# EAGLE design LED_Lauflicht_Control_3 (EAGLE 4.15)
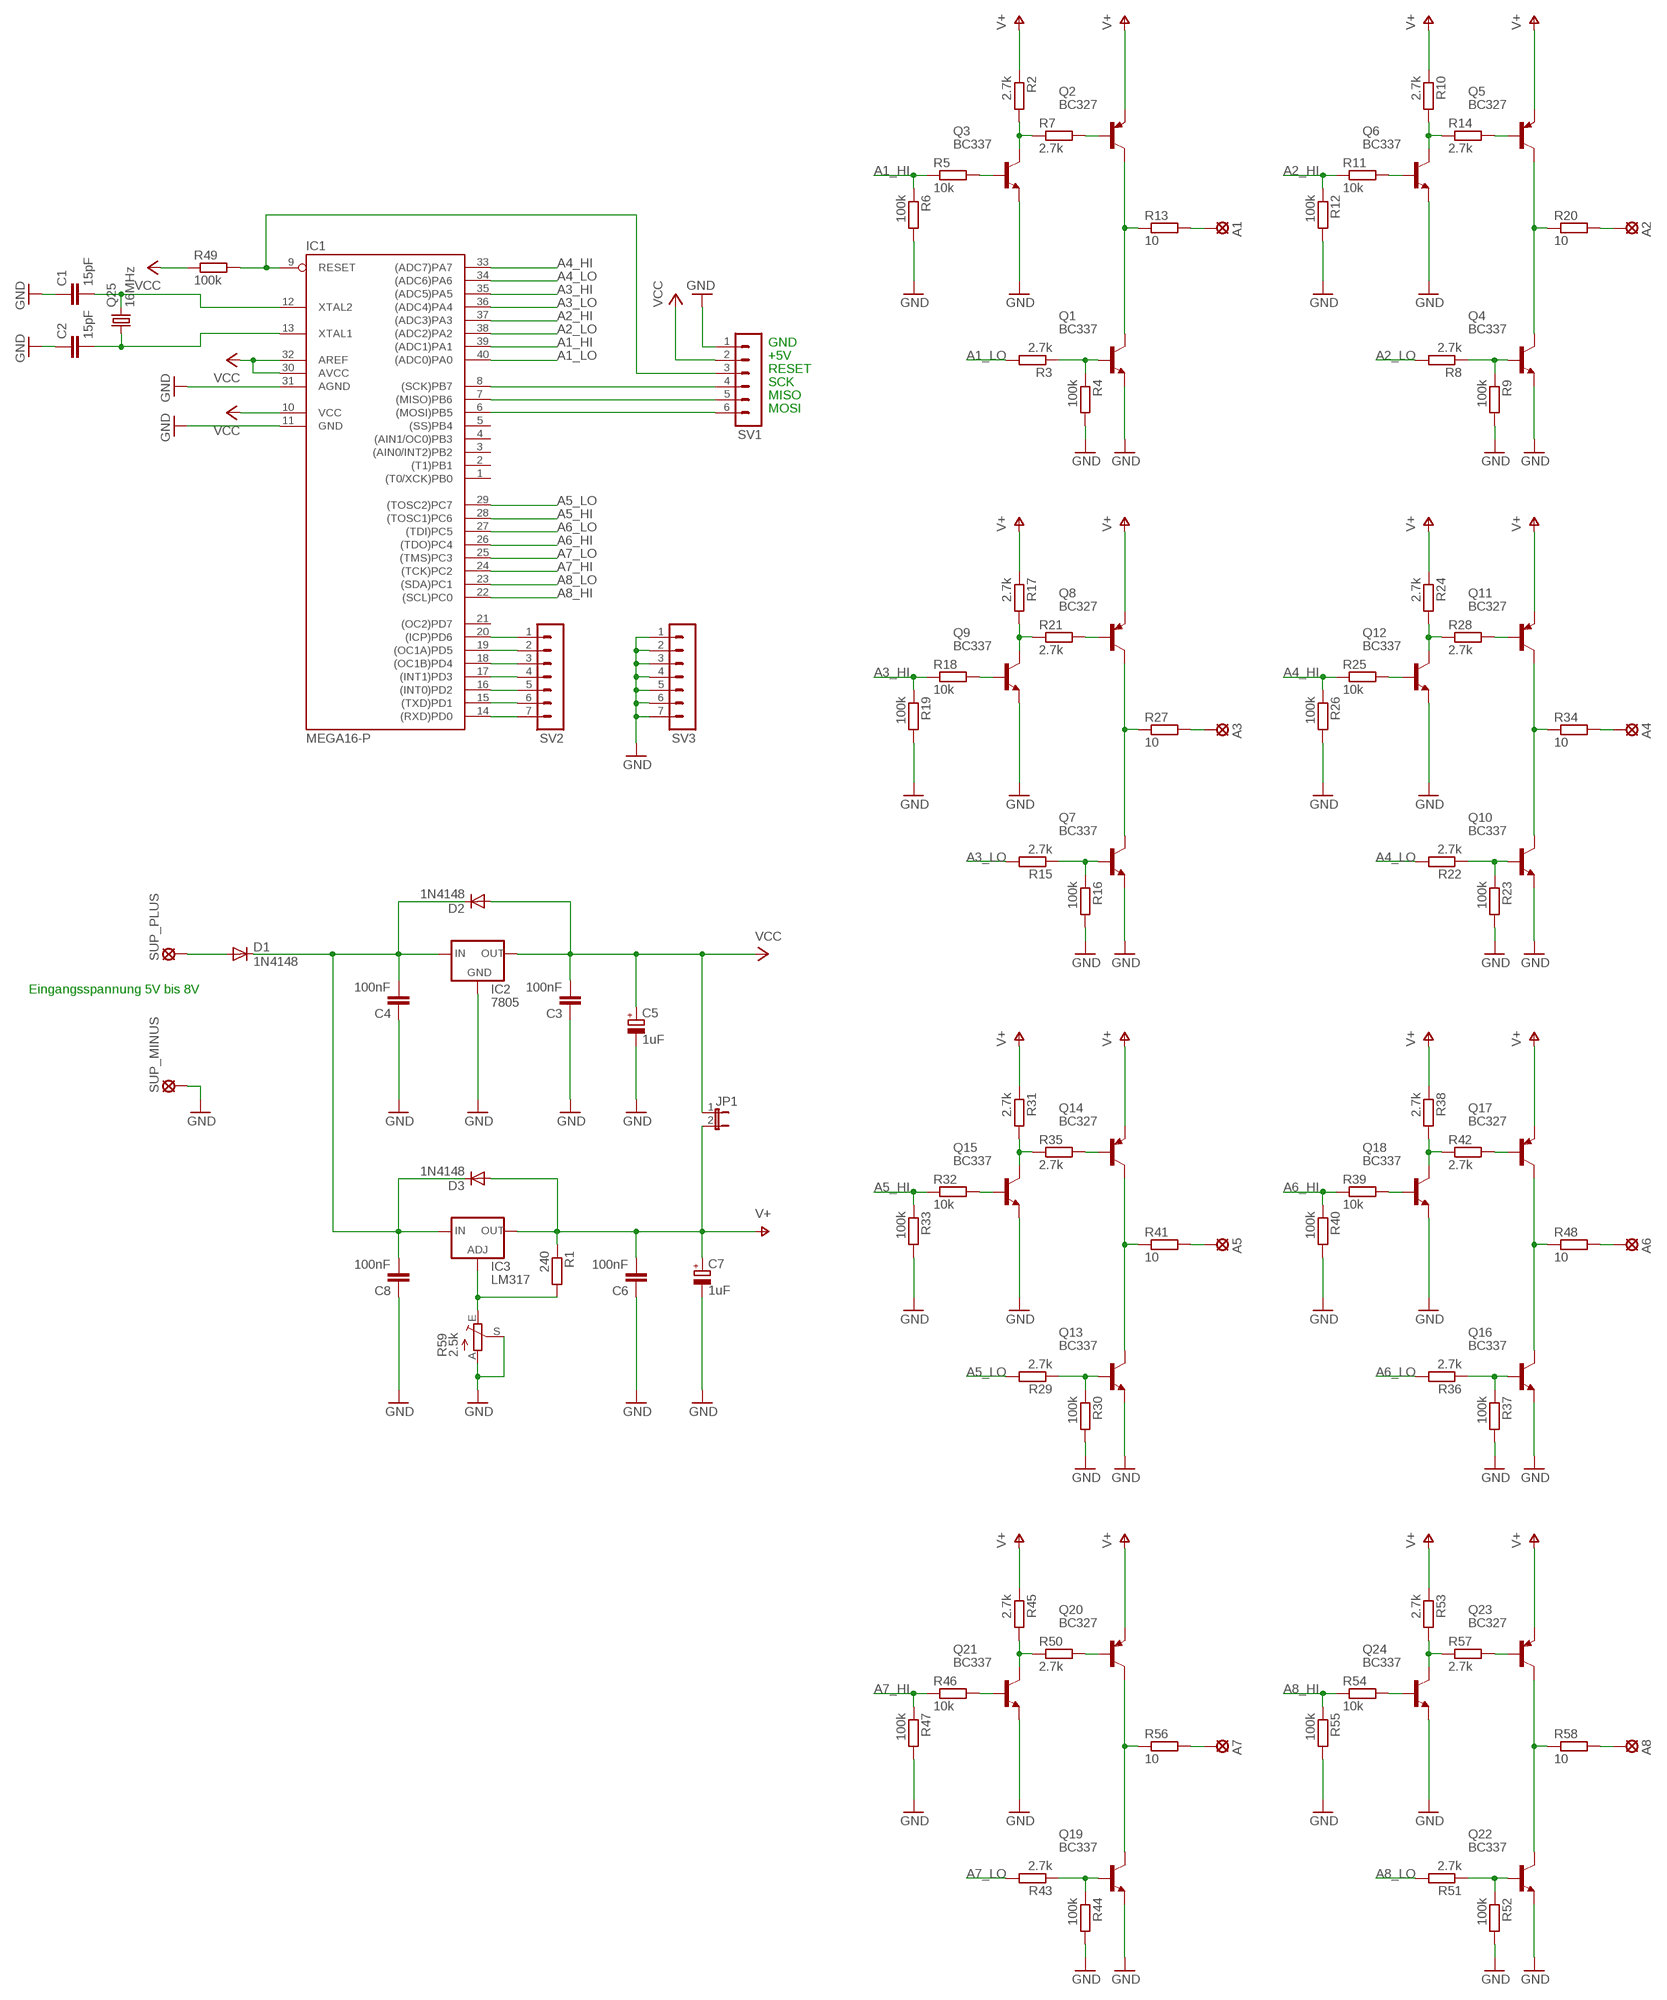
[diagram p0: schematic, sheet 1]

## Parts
A1  LSP13  [LSP13]
A2  LSP13  [LSP13]
A3  LSP13  [LSP13]
A4  LSP13  [LSP13]
A5  LSP13  [LSP13]
A6  LSP13  [LSP13]
A7  LSP13  [LSP13]
A8  LSP13  [LSP13]
C1  15pF  C-EU050-025X075  [C050-025X075]
C2  15pF  C-EU050-025X075  [C050-025X075]
C3  100nF  C-EU050-025X075  [C050-025X075]
C4  100nF  C-EU050-025X075  [C050-025X075]
C5  1uF  CPOL-EUE5-10.5  [E5-10,5]
C6  100nF  C-EU050-025X075  [C050-025X075]
C7  1uF  CPOL-EUE5-10.5  [E5-10,5]
C8  100nF  C-EU050-025X075  [C050-025X075]
D1  1N4148  [DO35-10]
D2  1N4148  [DO35-10]
D3  1N4148  [DO35-10]
IC1  MEGA16-P  [DIL40]
IC2  7805  78XXL  [78XXL]
IC3  LM317  LM317TL  [317TL]
JP1  JP1E  [JP1]
Q1  BC337  BC549B  [TO92-EBC]
Q2  BC327  BC559B  [TO92-EBC]
Q3  BC337  BC549B  [TO92-EBC]
Q4  BC337  BC549B  [TO92-EBC]
Q5  BC327  BC559B  [TO92-EBC]
Q6  BC337  BC549B  [TO92-EBC]
Q7  BC337  BC549B  [TO92-EBC]
Q8  BC327  BC559B  [TO92-EBC]
Q9  BC337  BC549B  [TO92-EBC]
Q10  BC337  BC549B  [TO92-EBC]
Q11  BC327  BC559B  [TO92-EBC]
Q12  BC337  BC549B  [TO92-EBC]
Q13  BC337  BC549B  [TO92-EBC]
Q14  BC327  BC559B  [TO92-EBC]
Q15  BC337  BC549B  [TO92-EBC]
Q16  BC337  BC549B  [TO92-EBC]
Q17  BC327  BC559B  [TO92-EBC]
Q18  BC337  BC549B  [TO92-EBC]
Q19  BC337  BC549B  [TO92-EBC]
Q20  BC327  BC559B  [TO92-EBC]
Q21  BC337  BC549B  [TO92-EBC]
Q22  BC337  BC549B  [TO92-EBC]
Q23  BC327  BC559B  [TO92-EBC]
Q24  BC337  BC549B  [TO92-EBC]
Q25  16MHz  CRYTALHC18U-V  [HC18U-V]
R1  240  R-EU_0207/10  [0207/10]
R2  2.7k  R-EU_0207/10  [0207/10]
R3  2.7k  R-EU_0207/10  [0207/10]
R4  100k  R-EU_0207/10  [0207/10]
R5  10k  R-EU_0207/10  [0207/10]
R6  100k  R-EU_0207/10  [0207/10]
R7  2.7k  R-EU_0207/10  [0207/10]
R8  2.7k  R-EU_0207/10  [0207/10]
R9  100k  R-EU_0207/10  [0207/10]
R10  2.7k  R-EU_0207/10  [0207/10]
R11  10k  R-EU_0207/10  [0207/10]
R12  100k  R-EU_0207/10  [0207/10]
R13  10  R-EU_0207/10  [0207/10]
R14  2.7k  R-EU_0207/10  [0207/10]
R15  2.7k  R-EU_0207/10  [0207/10]
R16  100k  R-EU_0207/10  [0207/10]
R17  2.7k  R-EU_0207/10  [0207/10]
R18  10k  R-EU_0207/10  [0207/10]
R19  100k  R-EU_0207/10  [0207/10]
R20  10  R-EU_0207/10  [0207/10]
R21  2.7k  R-EU_0207/10  [0207/10]
R22  2.7k  R-EU_0207/10  [0207/10]
R23  100k  R-EU_0207/10  [0207/10]
R24  2.7k  R-EU_0207/10  [0207/10]
R25  10k  R-EU_0207/10  [0207/10]
R26  100k  R-EU_0207/10  [0207/10]
R27  10  R-EU_0207/10  [0207/10]
R28  2.7k  R-EU_0207/10  [0207/10]
R29  2.7k  R-EU_0207/10  [0207/10]
R30  100k  R-EU_0207/10  [0207/10]
R31  2.7k  R-EU_0207/10  [0207/10]
R32  10k  R-EU_0207/10  [0207/10]
R33  100k  R-EU_0207/10  [0207/10]
R34  10  R-EU_0207/10  [0207/10]
R35  2.7k  R-EU_0207/10  [0207/10]
R36  2.7k  R-EU_0207/10  [0207/10]
R37  100k  R-EU_0207/10  [0207/10]
R38  2.7k  R-EU_0207/10  [0207/10]
R39  10k  R-EU_0207/10  [0207/10]
R40  100k  R-EU_0207/10  [0207/10]
R41  10  R-EU_0207/10  [0207/10]
R42  2.7k  R-EU_0207/10  [0207/10]
R43  2.7k  R-EU_0207/10  [0207/10]
R44  100k  R-EU_0207/10  [0207/10]
R45  2.7k  R-EU_0207/10  [0207/10]
R46  10k  R-EU_0207/10  [0207/10]
R47  100k  R-EU_0207/10  [0207/10]
R48  10  R-EU_0207/10  [0207/10]
R49  100k  R-EU_0207/10  [0207/10]
R50  2.7k  R-EU_0207/10  [0207/10]
R51  2.7k  R-EU_0207/10  [0207/10]
R52  100k  R-EU_0207/10  [0207/10]
R53  2.7k  R-EU_0207/10  [0207/10]
R54  10k  R-EU_0207/10  [0207/10]
R55  100k  R-EU_0207/10  [0207/10]
R56  10  R-EU_0207/10  [0207/10]
R57  2.7k  R-EU_0207/10  [0207/10]
R58  10  R-EU_0207/10  [0207/10]
R59  2.5k  TRIM_EU-LI15  [LI15]
SUP_MINUS  LSP13  [LSP13]
SUP_PLUS  LSP13  [LSP13]
SV1  MA06-1  [MA06-1]
SV2  MA07-1  [MA07-1]
SV3  MA07-1  [MA07-1]

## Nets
A1_HI: IC1.39((ADC1)PA1) R5.1 R6.1
A1_LO: IC1.40((ADC0)PA0) R3.2
A2_HI: IC1.37((ADC3)PA3) R11.1 R12.1
A2_LO: IC1.38((ADC2)PA2) R8.2
A3_HI: IC1.35((ADC5)PA5) R18.1 R19.1
A3_LO: IC1.36((ADC4)PA4) R15.2
A4_HI: IC1.33((ADC7)PA7) R25.1 R26.1
A4_LO: IC1.34((ADC6)PA6) R22.2
A5_HI: IC1.28((TOSC1)PC6) R32.1 R33.1
A5_LO: IC1.29((TOSC2)PC7) R29.2
A6_HI: IC1.26((TDO)PC4) R39.1 R40.1
A6_LO: IC1.27((TDI)PC5) R36.2
A7_HI: IC1.24((TCK)PC2) R46.1 R47.1
A7_LO: IC1.25((TMS)PC3) R43.2
A8_HI: IC1.22((SCL)PC0) R54.1 R55.1
A8_LO: IC1.23((SDA)PC1) R51.2
GND: C1.1 C2.1 C3.1 C4.1 C5.- C6.1 C7.- C8.1 IC1.11(GND) IC1.31(AGND) IC2.GND Q1.E Q3.E Q4.E Q6.E Q7.E Q9.E Q10.E Q12.E Q13.E Q15.E Q16.E Q18.E Q19.E Q21.E Q22.E Q24.E R4.2 R6.2 R9.2 R12.2 R16.2 R19.2 R23.2 R26.2 R30.2 R33.2 R37.2 R40.2 R44.2 R47.2 R52.2 R55.2 R59.A R59.S SUP_MINUS.MP SV1.1 SV3.1 SV3.2 SV3.3 SV3.4 SV3.5 SV3.6 SV3.7
N$1: Q1.C Q2.C R13.1
N$2: Q3.C R2.2 R7.1
N$3: Q3.B R5.2
N$4: Q2.B R7.2
N$5: Q4.C Q5.C R20.1
N$6: Q6.C R10.2 R14.1
N$7: IC1.14((RXD)PD0) SV2.7
N$8: C4.2 C8.2 D1.C D2.C D3.C IC2.IN IC3.3(IN)
N$9: Q4.B R8.1 R9.1
N$10: Q6.B R11.2
N$11: Q5.B R14.2
N$12: Q7.C Q8.C R27.1
N$13: Q9.C R17.2 R21.1
N$14: IC1.15((TXD)PD1) SV2.6
N$15: Q7.B R15.1 R16.1
N$16: Q9.B R18.2
N$17: Q8.B R21.2
N$18: Q10.C Q11.C R34.1
N$19: Q12.C R24.2 R28.1
N$20: IC1.16((INT0)PD2) SV2.5
N$21: Q1.B R3.1 R4.1
N$22: Q10.B R22.1 R23.1
N$23: Q12.B R25.2
N$24: Q11.B R28.2
N$25: Q13.C Q14.C R41.1
N$26: Q15.C R31.2 R35.1
N$27: IC1.17((INT1)PD3) SV2.4
N$28: Q13.B R29.1 R30.1
N$29: Q15.B R32.2
N$30: Q14.B R35.2
N$31: Q16.C Q17.C R48.1
N$32: Q18.C R38.2 R42.1
N$33: IC1.18((OC1B)PD4) SV2.3
N$34: Q16.B R36.1 R37.1
N$35: Q18.B R39.2
N$36: Q17.B R42.2
N$37: Q19.C Q20.C R56.1
N$38: C1.2 IC1.12(XTAL2) Q25.2
N$39: IC1.9(RESET) R49.2 SV1.3
N$40: Q21.C R45.2 R50.1
N$41: IC1.19((OC1A)PD5) SV2.2
N$42: Q19.B R43.1 R44.1
N$43: C2.2 IC1.13(XTAL1) Q25.1
N$44: IC1.7((MISO)PB6) SV1.5
N$45: Q21.B R46.2
N$46: IC1.8((SCK)PB7) SV1.4
N$47: Q20.B R50.2
N$48: Q22.C Q23.C R58.1
N$49: IC1.6((MOSI)PB5) SV1.6
N$50: Q24.C R53.2 R57.1
N$51: IC1.20((ICP)PD6) SV2.1
N$52: Q22.B R51.1 R52.1
N$53: Q24.B R54.2
N$54: Q23.B R57.2
N$55: D1.A SUP_PLUS.MP
N$56: A1.MP R13.2
N$57: A2.MP R20.2
N$58: A3.MP R27.2
N$59: A4.MP R34.2
N$60: A5.MP R41.2
N$61: A6.MP R48.2
N$62: A7.MP R56.2
N$63: A8.MP R58.2
N$65: IC3.1(ADJ) R1.2 R59.E
V+: C6.2 C7.+ D3.A IC3.2(OUT) JP1.2 Q2.E Q5.E Q8.E Q11.E Q14.E Q17.E Q20.E Q23.E R1.1 R2.1 R10.1 R17.1 R24.1 R31.1 R38.1 R45.1 R53.1
VCC: C3.2 C5.+ D2.A IC1.10(VCC) IC1.30(AVCC) IC1.32(AREF) IC2.OUT JP1.1 R49.1 SV1.2
Unconnected: IC1.1((T0/XCK)PB0) IC1.2((T1)PB1) IC1.3((AIN0/INT2)PB2) IC1.4((AIN1/OC0)PB3) IC1.5((SS)PB4) IC1.21((OC2)PD7)

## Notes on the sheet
- GND
- +5V
- RESET
- SCK
- MISO
- MOSI
- Eingangsspannung 5V bis 8V

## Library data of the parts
A1-A8 SUP_MINUS SUP_PLUS = solpad:LSP13: SOLDER PAD
C1-C4 C6 C8 = rcl:C-EU: CAPACITOR, European symbol
C5 C7 = rcl:CPOL-EU: POLARIZED CAPACITOR, European symbol
D1-D3 = diode:1N4148: DIODE
IC1 = avr:MEGA16-P: MICROCONTROLLER 16 Kbytes FLASH 1 kbytes SRAM 512 bytes EEPROM USART 8-channel 10 bit ADC
IC2 = v-reg:78XXL: VOLTAGE REGULATOR
IC3 = v-reg:LM317TL: VOLTAGE REGULATOR
JP1 = jumper:JP1E: JUMPER
Q1 Q3 Q4 Q6 Q7 Q9 Q10 Q12 Q13 Q15 Q16 Q18 Q19 Q21 Q22 Q24 = transistor-npn:BC549*: NPN Transistor
Q2 Q5 Q8 Q11 Q14 Q17 Q20 Q23 = transistor-pnp:BC559*: PNP Transistror
Q25 = crystal:CRYTAL: CRYSTAL
R1-R58 = rcl:R-EU_: RESISTOR, European symbol
R59 = pot:TRIM_EU-: POTENTIOMETER
SV1 = con-lstb:MA06-1: PIN HEADER
SV2 SV3 = con-lstb:MA07-1: PIN HEADER

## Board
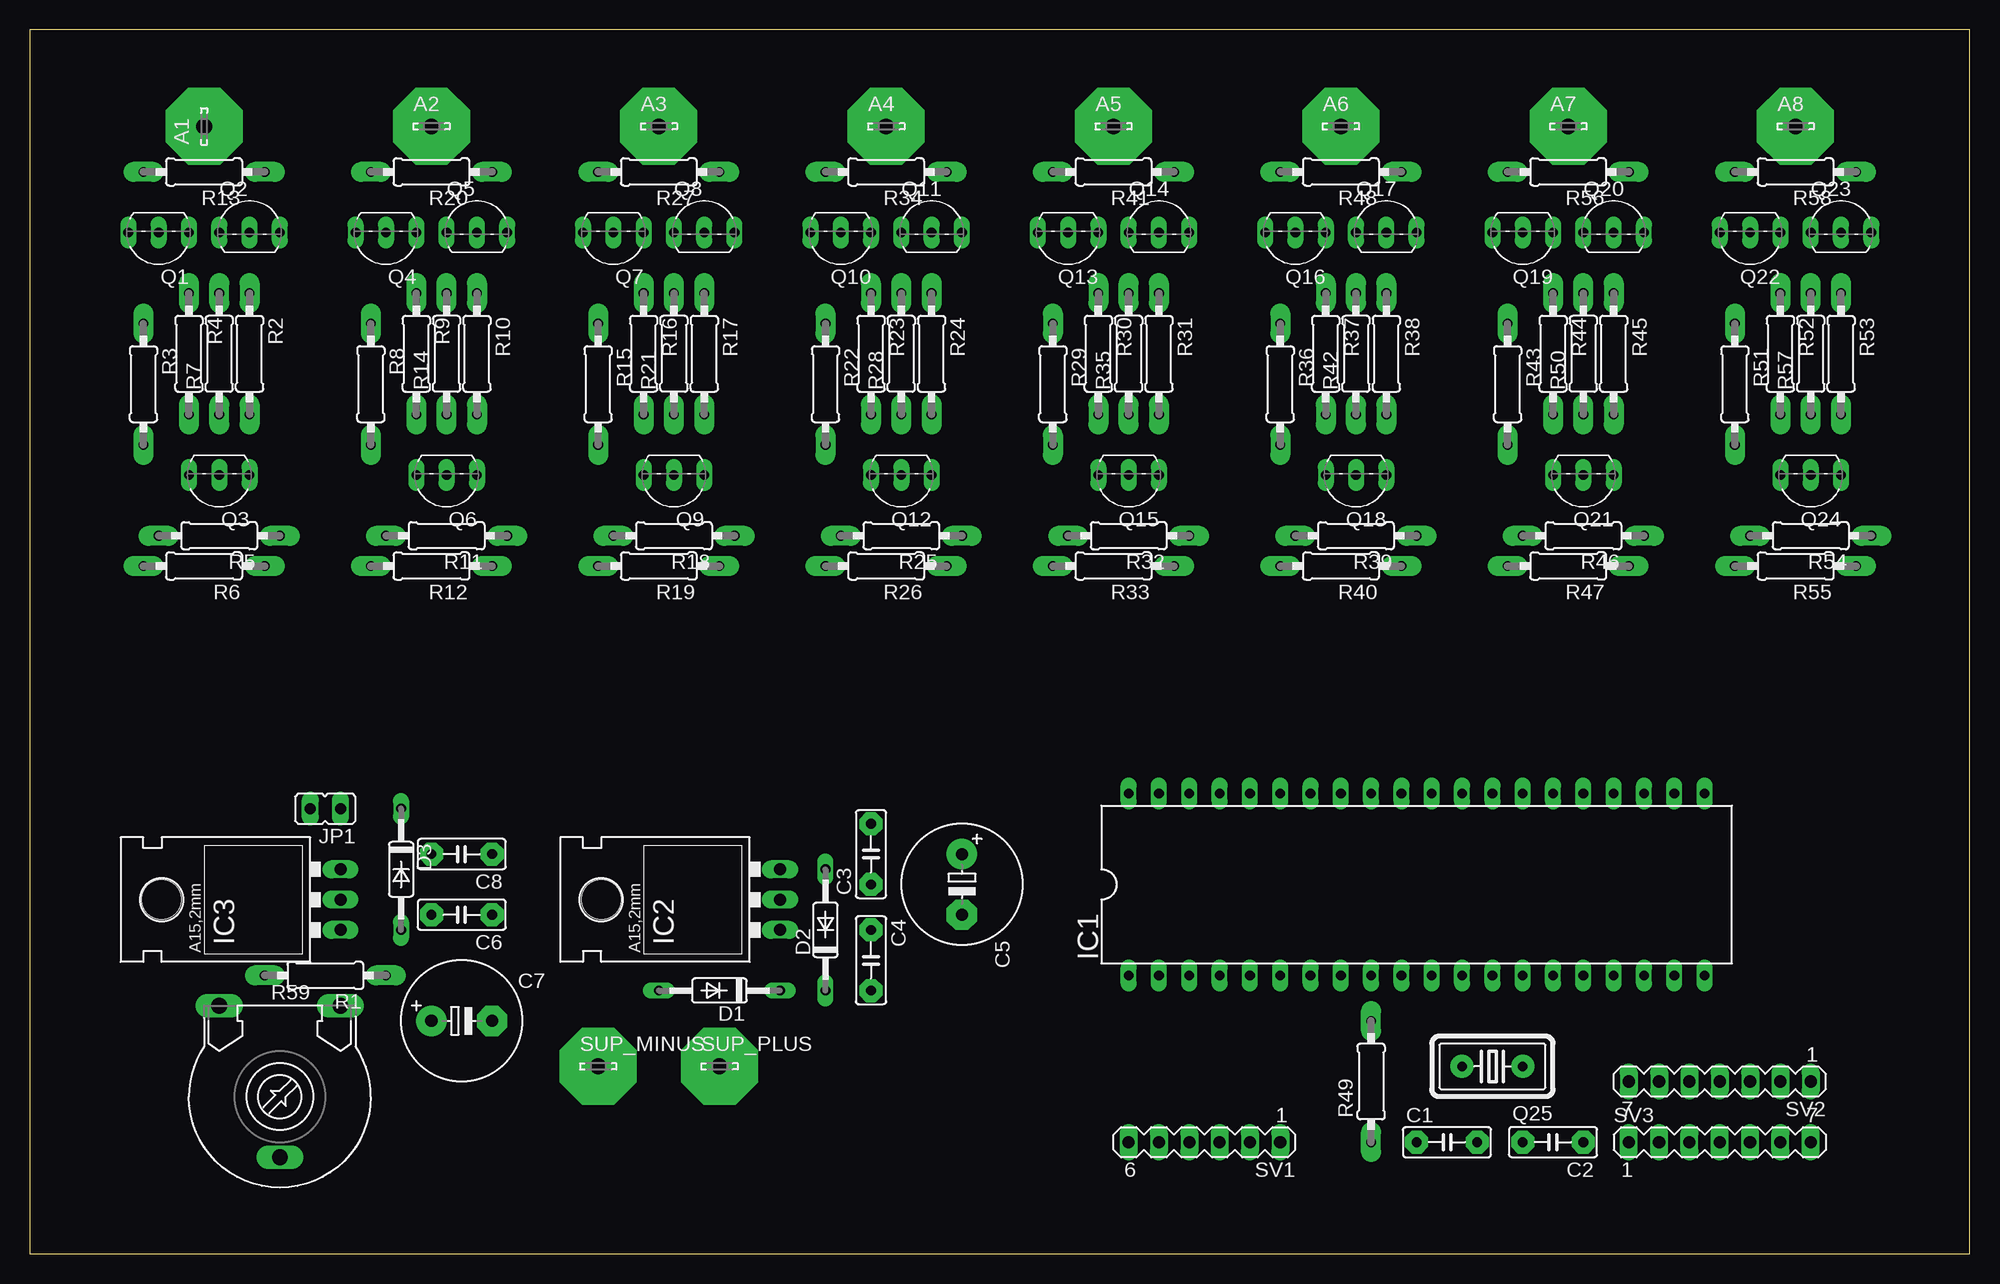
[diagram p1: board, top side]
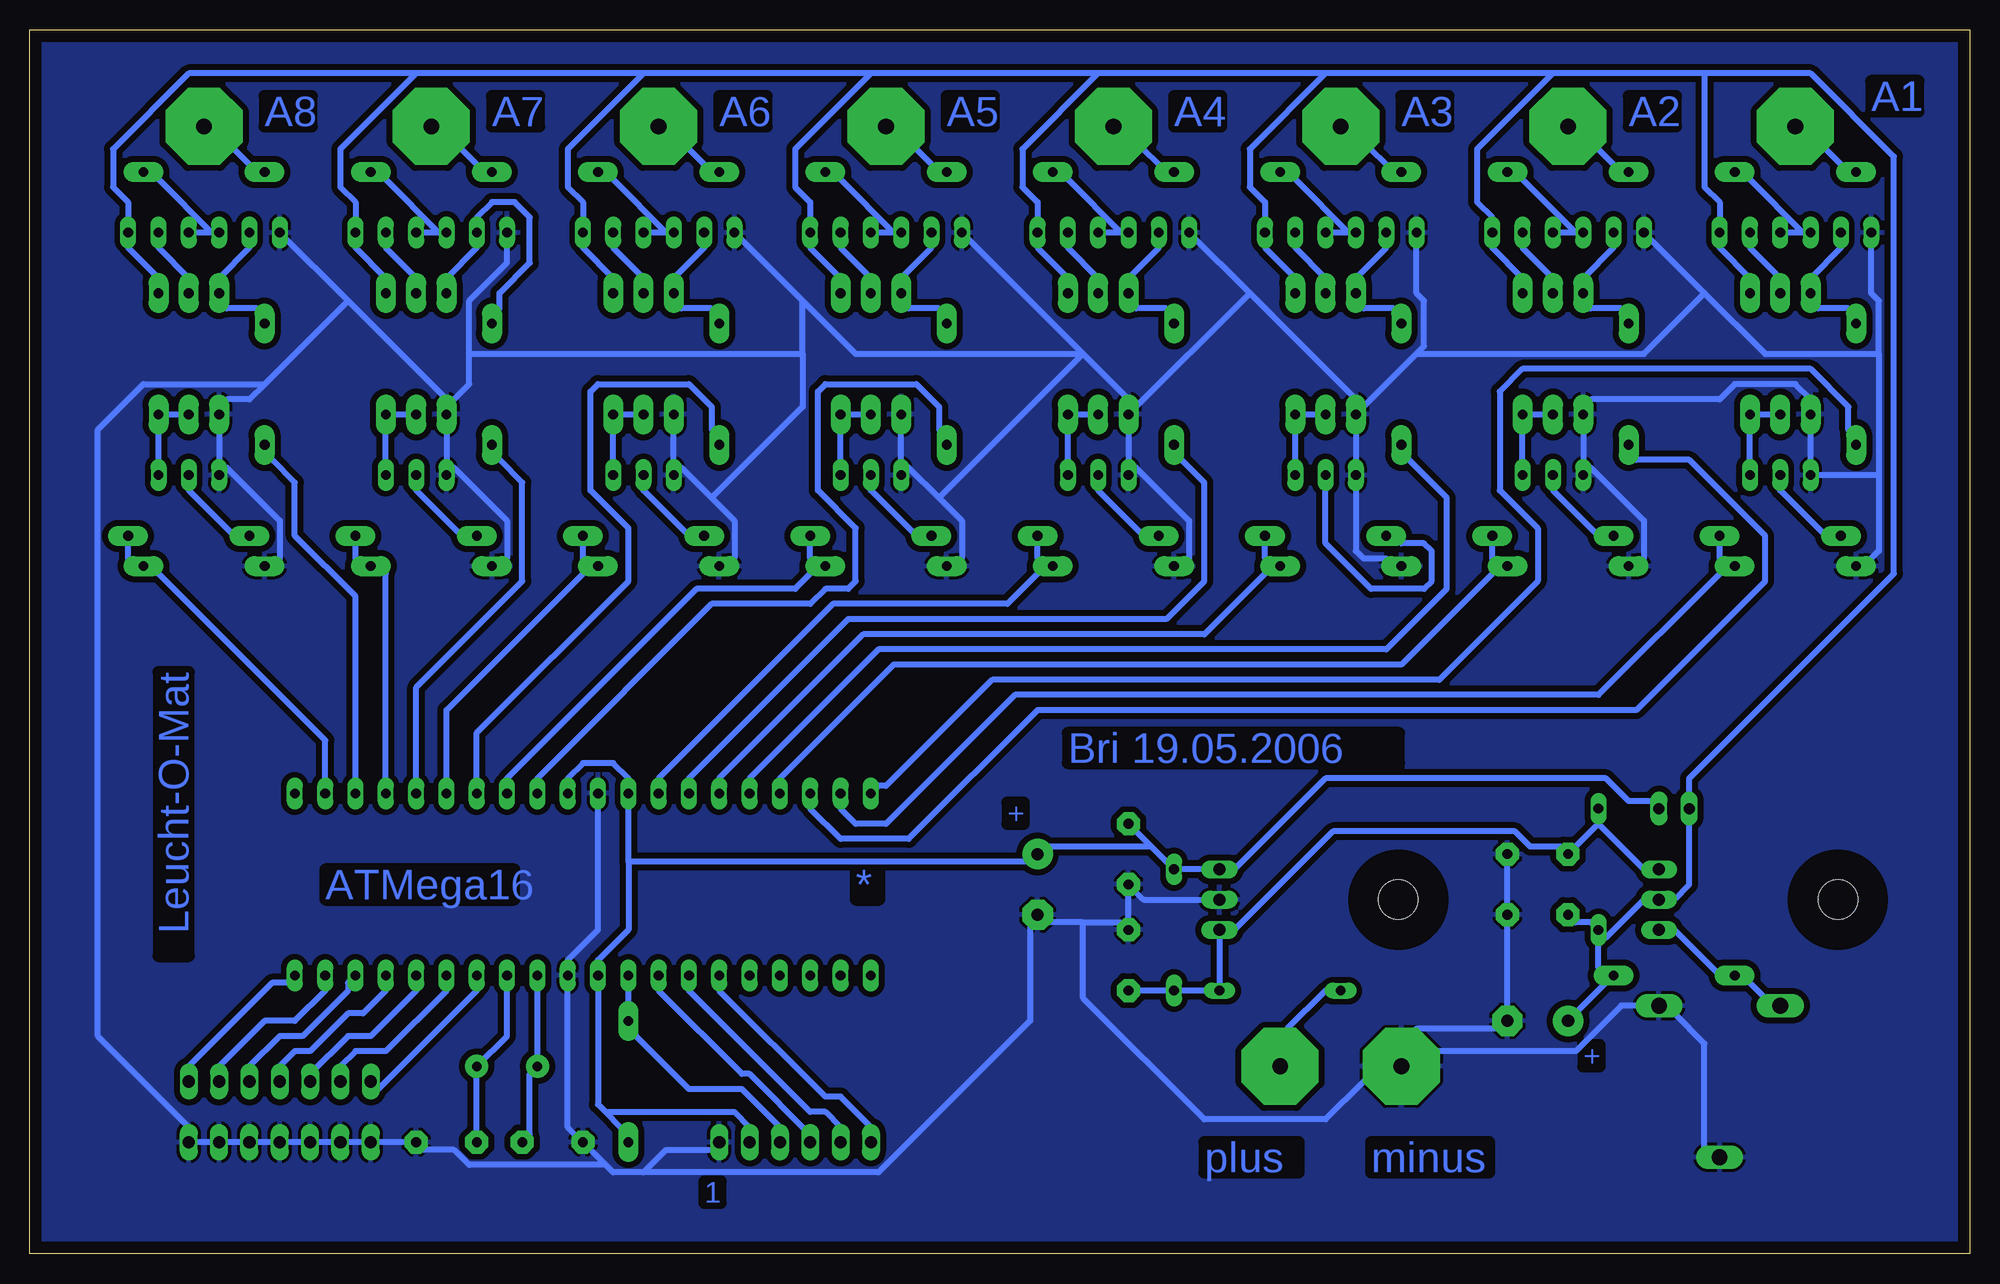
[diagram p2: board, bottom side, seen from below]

Size 162.54 x 102.54 mm. Coordinates in mm from the lower left corner, seen from the top.
Outline: 0,0 162.54,0 162.54,102.54 0,102.54 0,0
Copper layers (1*16): Top 0.035mm / dielectric 1.5mm / Bottom 0.035mm
Design rules "default": minimum track width 0.5mm, minimum drill 0.4mm, track to track 0.5mm, track to pad 0.5mm, pad to pad 0.5mm, via to via 0.5mm, smd to smd 8mil, copper to edge 1mm, drill to drill 1mm, minimum pad ring 10mil, minimum via ring 8mil, stop-mask expansion 4mil, vias tented up to drill 0mil, thermal gap 10mil

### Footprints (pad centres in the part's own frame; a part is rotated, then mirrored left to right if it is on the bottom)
LSP13 = drill 1.321 pad 6.452 octagon: MP 0,0
C050-025X075 = drill 0.813 pad 1.93 octagon: 1 -2.54,0; 2 2.54,0
E5-10,5 = drill 1.016 pad 2.54 round: + -2.54,0 | drill 1.016 pad 2.54 octagon: - 2.54,0
DO35-10 = drill 0.813 long: A 5.08,0; C -5.08,0
DIL40 = drill 0.813 long: 1 -24.13,-7.62; 2 -21.59,-7.62; 3 -19.05,-7.62; 4 -16.51,-7.62; 5 -13.97,-7.62; 6 -11.43,-7.62; 7 -8.89,-7.62; 8 -6.35,-7.62; 9 -3.81,-7.62; 10 -1.27,-7.62; 11 1.27,-7.62; 12 3.81,-7.62; 13 6.35,-7.62; 14 8.89,-7.62; 15 11.43,-7.62; 16 13.97,-7.62; 17 16.51,-7.62; 18 19.05,-7.62; 19 21.59,-7.62; 20 24.13,-7.62; 21 24.13,7.62; 22 21.59,7.62; 23 19.05,7.62; 24 16.51,7.62; 25 13.97,7.62; 26 11.43,7.62; 27 8.89,7.62; 28 6.35,7.62; 29 3.81,7.62; 30 1.27,7.62; 31 -1.27,7.62; 32 -3.81,7.62; 33 -6.35,7.62; 34 -8.89,7.62; 35 -11.43,7.62; 36 -13.97,7.62; 37 -16.51,7.62; 38 -19.05,7.62; 39 -21.59,7.62; 40 -24.13,7.62
78XXL = drill 1.016 long: GND 0,-3.81; IN -2.54,-3.81; OUT 2.54,-3.81 | hole 3.302: 0,11.176
317TL = drill 1.016 long: 1 -2.54,-3.81; 2 0,-3.81; 3 2.54,-3.81 | hole 3.302: 0,11.176
JP1 = drill 0.914 long: 1 0,-1.27; 2 0,1.27
TO92-EBC = drill 0.813 long: B 0,-1.27; C -2.54,-1.27; E 2.54,-1.27
HC18U-V = drill 0.813 pad 1.93 round: 1 -2.54,0; 2 2.54,0
0207/10 = drill 0.813 pad 1.676 long: 1 -5.08,0; 2 5.08,0
LI15 = drill 1.321 long: A -5.08,-7.62; E 5.08,-7.62; S 0,5.08
MA06-1 = drill 1.016 long: 1 -6.35,0; 2 -3.81,0; 3 -1.27,0; 4 1.27,0; 5 3.81,0; 6 6.35,0
MA07-1 = drill 1.016 long: 1 -7.62,0; 2 -5.08,0; 3 -2.54,0; 4 0,0; 5 2.54,0; 6 5.08,0; 7 7.62,0

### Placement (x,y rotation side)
A1  14.6,94.45 90 top
A2  33.65,94.45 0 top
A3  52.7,94.45 0 top
A4  71.75,94.45 0 top
A5  90.8,94.45 0 top
A6  109.85,94.45 0 top
A7  128.9,94.45 0 top
A8  147.95,94.45 0 top
C1  118.74,9.36 0 top
C2  127.63,9.36 180 top
C3  70.48,33.49 90 top
C4  70.48,24.6 270 top
C5  78.1,30.95 270 top
C6  36.19,28.41 180 top
C7  36.19,19.52 0 top
C8  36.19,33.49 180 top
D1  57.78,22.06 180 top
D2  66.67,27.14 90 top
D3  31.11,32.22 270 top
IC1  116.2,30.95 0 top
IC2  59.05,29.68 90 top
IC3  22.22,29.68 90 top
JP1  24.76,37.3 90 top
Q1  10.79,84.29 180 top
Q2  18.41,86.83 0 top
Q3  15.87,63.97 180 top
Q4  29.84,84.29 180 top
Q5  37.46,86.83 0 top
Q6  34.92,63.97 180 top
Q7  48.89,84.29 180 top
Q8  56.51,86.83 0 top
Q9  53.97,63.97 180 top
Q10  67.94,84.29 180 top
Q11  75.56,86.83 0 top
Q12  73.02,63.97 180 top
Q13  86.99,84.29 180 top
Q14  94.61,86.83 0 top
Q15  92.07,63.97 180 top
Q16  106.04,84.29 180 top
Q17  113.66,86.83 0 top
Q18  111.12,63.97 180 top
Q19  125.09,84.29 180 top
Q20  132.71,86.83 0 top
Q21  130.17,63.97 180 top
Q22  144.14,84.29 180 top
Q23  151.76,86.83 0 top
Q24  149.22,63.97 180 top
Q25  122.55,15.71 180 top
R1  24.76,23.33 180 top
R2  18.41,75.4 270 top
R3  9.52,72.86 270 top
R4  13.33,75.4 270 top
R5  15.87,60.16 180 top
R6  14.6,57.62 180 top
R7  15.87,75.4 90 top
R8  28.57,72.86 270 top
R9  32.38,75.4 270 top
R10  37.46,75.4 270 top
R11  34.92,60.16 180 top
R12  33.65,57.62 180 top
R13  14.6,90.64 180 top
R14  34.92,75.4 90 top
R15  47.62,72.86 270 top
R16  51.43,75.4 270 top
R17  56.51,75.4 270 top
R18  53.97,60.16 180 top
R19  52.7,57.62 180 top
R20  33.65,90.64 180 top
R21  53.97,75.4 90 top
R22  66.67,72.86 270 top
R23  70.48,75.4 270 top
R24  75.56,75.4 270 top
R25  73.02,60.16 180 top
R26  71.75,57.62 180 top
R27  52.7,90.64 180 top
R28  73.02,75.4 90 top
R29  85.72,72.86 270 top
R30  89.53,75.4 270 top
R31  94.61,75.4 270 top
R32  92.07,60.16 180 top
R33  90.8,57.62 180 top
R34  71.75,90.64 180 top
R35  92.07,75.4 90 top
R36  104.77,72.86 270 top
R37  108.58,75.4 270 top
R38  113.66,75.4 270 top
R39  111.12,60.16 180 top
R40  109.85,57.62 180 top
R41  90.8,90.64 180 top
R42  111.12,75.4 90 top
R43  123.82,72.86 270 top
R44  127.63,75.4 270 top
R45  132.71,75.4 270 top
R46  130.17,60.16 180 top
R47  128.9,57.62 180 top
R48  109.85,90.64 180 top
R49  112.39,14.44 90 top
R50  130.17,75.4 90 top
R51  142.87,72.86 270 top
R52  146.68,75.4 270 top
R53  151.76,75.4 270 top
R54  149.22,60.16 180 top
R55  147.95,57.62 180 top
R56  128.9,90.64 180 top
R57  149.22,75.4 90 top
R58  147.95,90.64 180 top
R59  20.95,13.17 180 top
SUP_MINUS  47.62,15.71 0 top
SUP_PLUS  57.78,15.71 0 top
SV1  98.42,9.36 180 top
SV2  141.6,14.44 180 top
SV3  141.6,9.36 0 top

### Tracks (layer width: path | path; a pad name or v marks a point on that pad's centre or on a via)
A1_HI
  Bottom 0.5: R5.1 20.95,58.26 R6.1 20.95,56.98 31.11,46.83 80.01,46.83 90.8,36.03 93.34,36.03 94.61,37.3 IC1.39
A1_LO
  Bottom 0.5: IC1.40 91.44,39.21 90.8,39.21 81.91,48.09 44.45,48.09 36.19,56.35 36.19,60.8 39.37,63.97 39.37,72.22 37.46,74.13 13.33,74.13 10.16,70.95 10.16,69.05 R3.2
A2_HI
  Bottom 0.5: IC1.37 99.69,39.84 90.17,49.37 47.62,49.37 40,56.98 R12.1 40,58.26 R11.1
A2_LO
  Bottom 0.5: IC1.38 97.15,37.3 94.61,34.76 88.9,34.76 78.1,45.55 27.93,45.55 17.14,56.35 17.14,60.16 23.49,66.51 27.93,66.51 R8.2
A3_HI
  Bottom 0.5: IC1.35 104.77,39.84 92.71,51.91 64.13,51.91 59.05,56.98 R19.1 59.05,58.26 R18.1
A3_LO
  Bottom 0.5: IC1.36 102.23,39.84 91.44,50.64 48.89,50.64 43.81,55.72 43.81,63.34 46.98,66.51 R15.2
A4_HI
  Bottom 0.5: IC1.33 109.85,39.84 95.25,54.45 80.64,54.45 78.1,56.98 R26.1 78.1,58.26 R25.1
A4_LO
  Bottom 0.5: IC1.34 107.31,39.84 93.98,53.18 67.31,53.18 64.13,56.35 64.13,64.61 66.04,66.51 R22.2
A5_HI
  Bottom 0.5: IC1.28 122.55,39.84 106.68,55.72 98.42,55.72 97.15,56.98 R33.1 97.15,58.26 R32.1
A5_LO
  Bottom 0.5: IC1.29 120.01,39.84 105.41,54.45 97.15,54.45 95.88,55.72 93.98,55.72 93.34,56.35 93.34,60.8 96.52,63.97 96.52,72.22 95.88,72.86 88.26,72.86 86.36,70.95 86.36,69.05 R29.2
A6_HI
  Bottom 0.5: IC1.26 127.63,45.55 116.2,56.98 R40.1 116.2,58.26 R39.1
A6_LO
  Bottom 0.5: IC1.27 125.09,43.65 112.39,56.35 112.39,60.8 115.57,63.97 115.57,72.22 114.93,72.86 107.31,72.86 105.41,70.95 105.41,69.05 R36.2
A7_HI
  Bottom 0.5: IC1.24 132.71,56.98 R47.1 135.25,58.26 R46.1
A7_LO
  Bottom 0.5: IC1.25 130.17,47.46 121.28,56.35 121.28,64.61 123.19,66.51 R43.2
A8_HI
  Bottom 0.5: IC1.22 137.79,43.02 151.76,56.98 R55.1 154.3,58.26 R54.1
A8_LO
  Bottom 0.5: IC1.23 135.25,55.08 140.33,60.16 140.33,64.61 142.24,66.51 R51.2
GND
  Bottom 0.5: IC1.31 114.93,27.14 117.47,24.6 IC1.11 117.47,10.63 C1.1 114.3,7.46 | 111.12,6.82 109.22,8.72 105.41,8.72 SV1.1 | 111.12,6.82 113.66,6.82 114.3,7.46 | 114.3,7.46 125.73,7.46 127,8.72 129.53,8.72 C2.1 SV3.1 SV3.2 SV3.3 SV3.4 SV3.5 SV3.6 SV3.7 149.22,10.63 156.84,18.25 156.84,69.05 153.03,72.86 142.87,72.86 | IC2.GND 69.21,29.68 C3.1 C4.1 71.12,27.77 74.29,27.77 | R59.S 22.22,8.72 22.22,17.61 24.76,20.15 R59.A 29.2,20.79 33.02,16.98 44.45,16.98 SUP_MINUS.MP | C8.1 C6.1 C7.- 39.37,18.88 46.35,18.88 SUP_MINUS.MP | R55.2 141.6,58.26 141.6,61.43 146.05,65.88 Q24.E R52.2 146.05,71.59 144.14,71.59 142.87,72.86 | R44.2 Q21.E 127,65.88 122.55,61.43 122.55,58.26 R47.2 | 125.73,75.4 125.73,72.86 127,71.59 R44.2 | 125.73,75.4 125.73,79.84 122.55,83.02 Q19.E | 135.89,79.84 127.63,71.59 R44.2 | 135.89,79.84 Q22.E | 142.87,72.86 135.89,79.84 | R12.2 27.3,58.26 27.3,61.43 31.74,65.88 Q6.E R9.2 31.74,71.59 20.95,71.59 19.68,72.86 14.6,72.86 13.33,71.59 R4.2 Q3.E 7.62,65.24 | 7.62,65.24 7.62,58.89 8.25,58.26 R6.2 | 7.62,75.4 7.62,65.24 | 7.62,75.4 7.62,79.84 8.25,80.48 Q1.E | 22.22,80.48 17.14,75.4 7.62,75.4 | 22.22,80.48 Q4.E | R16.2 Q9.E 51.43,58.89 50.8,58.26 48.89,58.26 R19.2 | 46.35,75.4 45.71,76.03 45.71,79.84 46.35,80.48 Q7.E | R16.2 46.35,75.4 | 60.32,80.48 51.43,71.59 R16.2 | 60.32,80.48 Q10.E | R37.2 Q18.E 107.95,65.88 105.41,63.34 | 105.41,63.34 103.5,61.43 103.5,58.26 R40.2 | R30.2 Q15.E 88.9,65.88 86.36,63.34 | 86.36,63.34 84.45,61.43 84.45,58.26 R33.2 | R23.2 Q12.E 69.84,65.88 65.4,61.43 65.4,58.26 R26.2 | 74.29,75.4 70.48,71.59 R23.2 | 74.29,75.4 Q13.E | 97.79,79.84 93.34,75.4 74.29,75.4
  Bottom 0.5: 97.79,79.84 Q16.E | 74.29,75.4 86.36,63.34 | 105.41,63.34 97.79,70.95 97.79,75.4 | 97.79,75.4 97.79,79.84 | R23.2 60.32,80.48 | 22.22,80.48 27.3,75.4 46.35,75.4 | 125.73,75.4 97.79,75.4 | 74.29,27.77 77.47,27.77 C5.- 78.73,27.77 78.73,19.52 91.44,6.82 111.12,6.82 | 74.29,27.77 74.29,21.42 64.13,11.27 53.97,11.27 50.8,14.44 SUP_MINUS.MP
  pour Bottom: 0.63,102.07 161.92,102.07 161.92,0.47 0.63,0.47
N$1
  Bottom 0.5: 13.96,85.56 Q2.C | 13.96,85.56 18.41,90 R13.1 | Q1.C 13.96,85.56
N$2
  Bottom 0.5: Q3.C R2.2 R7.1
N$3
  Bottom 0.5: Q3.B 15.87,63.97 12.06,60.16 R5.2
N$4
  Bottom 0.5: Q2.B 18.41,84.29 15.87,81.75 R7.2
N$5
  Bottom 0.5: 33.02,85.56 Q5.C | 33.02,85.56 37.46,90 R20.1 | Q4.C 33.02,85.56
N$6
  Bottom 0.5: Q6.C R10.2 R14.1
N$7
  Bottom 0.5: IC1.14 125.09,22.06 133.34,13.8 SV2.7
N$8
  Bottom 0.5: 31.11,36.03 C8.2 34.28,34.12 36.82,34.12 38.09,35.4 53.34,35.4 61.59,27.14 IC2.IN D1.C D2.C C4.2 | 31.11,36.03 27.3,32.22 IC3.3 | 31.11,36.03 D3.C
N$9
  Bottom 0.5: Q4.B 29.84,84.29 32.38,81.75 R9.1 31.74,79.21 29.2,79.21 R8.1
N$10
  Bottom 0.5: Q6.B 34.92,63.97 31.11,60.16 R11.2
N$11
  Bottom 0.5: Q5.B 37.46,84.29 34.92,81.75 R14.2
N$12
  Bottom 0.5: 52.06,85.56 Q8.C | 52.06,85.56 56.51,90 R27.1 | Q7.C 52.06,85.56
N$13
  Bottom 0.5: Q9.C R17.2 R21.1
N$14
  Bottom 0.5: IC1.15 127.63,22.06 132.71,16.98 135.25,16.98 136.52,15.71 SV2.6
N$15
  Bottom 0.5: Q7.B 48.89,84.29 51.43,81.75 R16.1 50.8,79.21 48.25,79.21 R15.1
N$16
  Bottom 0.5: Q9.B 53.97,59.52 50.16,55.72 45.71,55.72 45.08,56.35 45.08,58.89 45.71,59.52 47.62,59.52 R18.2
N$17
  Bottom 0.5: Q8.B 56.51,84.29 53.97,81.75 R21.2
N$18
  Bottom 0.5: 71.12,85.56 Q11.C | 71.12,85.56 75.56,90 R34.1 | Q10.C 71.12,85.56
N$19
  Bottom 0.5: Q12.C R24.2 R28.1
N$20
  Bottom 0.5: IC1.16 130.17,22.06 133.98,18.25 135.89,18.25 139.06,15.08 SV2.5
N$21
  Bottom 0.5: Q1.B 10.79,84.29 13.33,81.75 R4.1 12.7,79.21 10.16,79.21 R3.1
N$22
  Bottom 0.5: Q10.B 67.94,84.29 70.48,81.75 R23.1 69.84,79.21 67.31,79.21 R22.1
N$23
  Bottom 0.5: Q12.B 73.02,63.97 69.21,60.16 R25.2
N$24
  Bottom 0.5: Q11.B 75.56,84.29 73.02,81.75 R28.2
N$25
  Bottom 0.5: 90.17,85.56 Q14.C | 90.17,85.56 94.61,90 R41.1 | Q13.C 90.17,85.56
N$26
  Bottom 0.5: Q15.C R31.2 R35.1
N$27
  Bottom 0.5: IC1.17 132.71,22.06 134.62,20.15 135.89,20.15 139.06,16.98 140.33,16.98 141.6,15.71 SV2.4
N$28
  Bottom 0.5: Q13.B 86.99,84.29 89.53,81.75 R30.1 88.9,79.21 86.36,79.21 R29.1
N$29
  Bottom 0.5: Q15.B 92.07,63.97 88.26,60.16 R32.2
N$30
  Bottom 0.5: Q14.B 94.61,84.29 92.07,81.75 R35.2
N$31
  Bottom 0.5: 109.22,85.56 Q17.C | 109.22,85.56 113.66,90 R48.1 | Q16.C 109.22,85.56
N$32
  Bottom 0.5: Q18.C R38.2 R42.1
N$33
  Bottom 0.5: IC1.18 135.89,22.69 135.89,22.06 139.69,18.25 141.6,18.25 144.14,15.71 SV2.3
N$34
  Bottom 0.5: Q16.B 106.04,84.29 108.58,81.75 R37.1 107.95,79.21 105.41,79.21 R36.1
N$35
  Bottom 0.5: Q18.B 111.12,63.97 107.31,60.16 R39.2
N$36
  Bottom 0.5: Q17.B 113.66,84.29 111.12,81.75 R42.2
N$37
  Bottom 0.5: 128.26,85.56 Q20.C | 128.26,85.56 132.71,90 R56.1 | Q19.C 128.26,85.56
N$38
  Bottom 0.5: IC1.12 Q25.2 120.65,15.08 120.65,10 C1.2
N$39
  Bottom 0.5: IC1.9 R49.2 111.76,18.25 107.31,13.8 102.87,13.8 99.69,10.63 SV1.3
N$40
  Bottom 0.5: Q21.C R45.2 R50.1
N$41
  Bottom 0.5: IC1.19 137.79,22.06 140.33,19.52 142.87,19.52 146.68,15.71 SV2.2
N$42
  Bottom 0.5: R44.1 127.63,81.75 125.09,84.29 Q19.B 125.09,86.83 123.82,88.1 121.92,88.1 120.65,86.83 120.65,83.02 123.19,80.48 123.19,79.21 R43.1
N$43
  Bottom 0.5: IC1.13 122.55,18.25 Q25.1 C2.2
N$44
  Bottom 0.5: IC1.7 107.31,22.06 97.15,11.9 95.88,11.9 94.61,10.63 SV1.5
N$45
  Bottom 0.5: Q21.B 130.17,63.97 126.36,60.16 R46.2
N$46
  Bottom 0.5: IC1.8 109.85,22.06 102.87,15.08 102.23,15.08 97.15,10 SV1.4
N$47
  Bottom 0.5: Q20.B 132.71,84.29 130.17,81.75 R50.2
N$48
  Bottom 0.5: 147.31,85.56 Q23.C | 147.31,85.56 151.76,90 R58.1 | Q22.C 147.31,85.56
N$49
  Bottom 0.5: IC1.6 104.77,22.06 95.88,13.17 94.61,13.17 92.07,10.63 SV1.6
N$50
  Bottom 0.5: Q24.C R53.2 R57.1
N$51
  Bottom 0.5: IC1.20 140.97,22.69 142.24,22.69 149.22,15.71 SV2.1
N$52
  Bottom 0.5: Q22.B 144.14,84.29 146.68,81.75 R52.1 146.05,79.21 143.5,79.21 R51.1
N$53
  Bottom 0.5: Q24.B 149.22,63.97 145.41,60.16 R54.2
N$54
  Bottom 0.5: Q23.B 151.76,84.29 149.22,81.75 R57.2
N$55
  Bottom 0.5: D1.A 53.97,22.06 57.14,18.88 SUP_PLUS.MP
N$56
  Bottom 0.5: R13.2 10.79,91.27 12.06,92.55 A1.MP
N$57
  Bottom 0.5: R20.2 29.84,91.27 31.11,92.55 A2.MP
N$58
  Bottom 0.5: R27.2 48.89,91.27 50.16,92.55 A3.MP
N$59
  Bottom 0.5: R34.2 67.94,91.27 69.21,92.55 A4.MP
N$60
  Bottom 0.5: R41.2 86.99,91.27 88.26,92.55 A5.MP
N$61
  Bottom 0.5: R48.2 106.04,91.27 107.31,92.55 A6.MP
N$62
  Bottom 0.5: R56.2 125.09,91.27 126.36,92.55 A7.MP
N$63
  Bottom 0.5: R58.2 144.14,91.27 145.41,92.55 A8.MP
N$65
  Bottom 0.5: IC3.1 24.76,27.14 20.95,23.33 R1.2 18.41,22.69 17.14,21.42 R59.E
V+
  Bottom 0.5: D3.A 31.74,27.77 33.02,27.77 C6.2 | D3.A 30.47,26.5 27.3,29.68 IC3.2 24.76,29.68 23.49,30.95 JP1.2 23.49,39.84 6.35,56.98 6.35,91.91 13.33,98.89 22.22,98.89 | D3.A 31.11,23.96 R1.1 C7.+ | R53.1 151.76,81.75 154.3,84.29 Q23.E 154.3,88.1 155.57,89.37 155.57,92.55 149.22,98.89 130.17,98.89 | R45.1 132.71,81.75 135.25,84.29 Q20.E 135.25,88.1 136.52,89.37 136.52,92.55 130.17,98.89 | R38.1 113.66,81.75 116.2,84.29 Q17.E 116.2,88.1 117.47,89.37 117.47,92.55 111.12,98.89 | R31.1 94.61,81.75 97.15,84.29 Q14.E 97.15,88.1 98.42,89.37 98.42,92.55 92.07,98.89 | R24.1 75.56,81.75 78.1,84.29 Q11.E 78.1,88.1 79.37,89.37 79.37,92.55 73.02,98.89 | R17.1 56.51,81.75 59.05,84.29 Q8.E 59.05,88.1 60.32,89.37 60.32,92.55 53.97,98.89 | R2.1 18.41,81.75 20.95,84.29 Q2.E 20.95,88.1 22.22,89.37 22.22,98.89 | R10.1 37.46,81.75 40,84.29 Q5.E 40,86.83 41.27,88.1 41.27,92.55 34.92,98.89 | 22.22,98.89 34.92,98.89 | 34.92,98.89 53.97,98.89 | 53.97,98.89 73.02,98.89 | 73.02,98.89 92.07,98.89 | 92.07,98.89 111.12,98.89 | 111.12,98.89 130.17,98.89
VCC
  Bottom 0.5: 68.58,34.12 C3.2 | 68.58,34.12 D2.A IC2.OUT 61.59,32.22 53.97,39.84 30.47,39.84 28.57,37.94 26.66,37.94 JP1.1 | 68.58,34.12 77.47,34.12 C5.+ 78.73,32.85 112.39,32.85 | 114.3,11.9 113.03,10.63 R49.1 | 114.3,11.9 114.93,12.54 IC1.10 114.93,24.6 112.39,27.14 112.39,32.85 | IC1.30 117.47,39.84 116.2,41.11 113.66,41.11 112.39,39.84 IC1.32 112.39,32.85 | 114.3,11.9 103.5,11.9 102.23,10.63 SV1.2

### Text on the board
Bottom: A1 | A2 | A3 | A4 | A5 | A6 | A7 | A8 | Leucht-O-Mat | Bri 19.05.2006 | + | * | ATMega16 | + | minus | plus | 1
